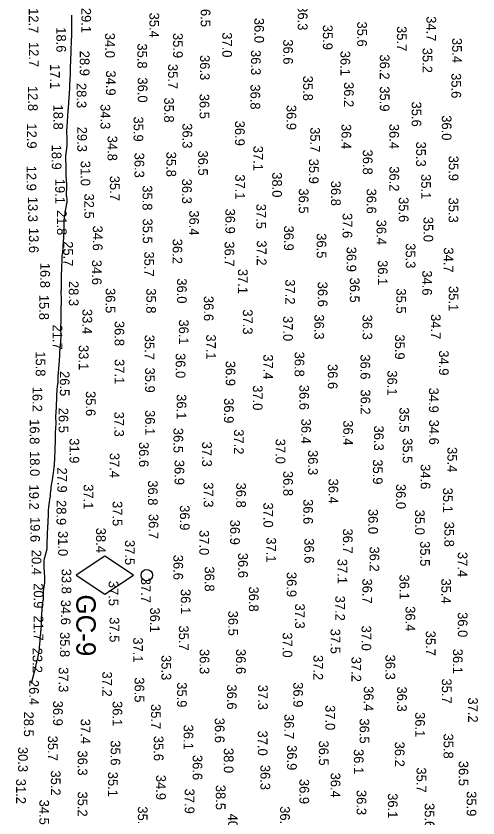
# Model space of a CAD drawing. Extents: x 1178573 to 1187098, y 693282 to 751751.
# Drawn here: x 1179031 to 1179627, y 707251 to 708287 of the extents above; entities that cross this region are included whole.
import ezdxf

# ---------------------------------------------------------------- set-up
doc = ezdxf.new("R2010")
doc.units = 0
for name, color, linetype in [('V-CHAN-NAID', 7, 'Continuous'), ('V-HYDS-MAJR', 7, 'Continuous'), ('V-HYDS-SOUN', 7, 'Continuous'), ('V-HYDS-SOUN-EXSS', 7, 'Continuous')]:
    doc.layers.add(name, color=color, linetype=linetype)

msp = doc.modelspace()

# ---------------------------------------------------------------- linework, layer by layer
at = {"layer": 'V-CHAN-NAID'}
msp.add_lwpolyline([(1179182.1, 707564.8), (1179145.2, 707589.4), (1179108.2, 707564.8), (1179145.2, 707540.1)], close=True, dxfattribs=at)
msp.add_circle((1179199.4, 707564.8), 7.39, dxfattribs=at)
at = {"layer": 'V-HYDS-MAJR'}
msp.add_lwpolyline([(1179050.4, 707425.1), (1179050.4, 707425.3), (1179055.1, 707441.7), (1179055.2, 707442.1), (1179055.3, 707442.6), (1179055.4, 707443.1), (1179055.5, 707443.6), (1179055.9, 707445.5), (1179056, 707445.9), (1179056.1, 707446.4), (1179056.3, 707446.9), (1179056.4, 707447.4), (1179059.2, 707459.6), (1179059.4, 707460.6), (1179059.6, 707461.6), (1179059.8, 707462.6), (1179060, 707463.6), (1179060.7, 707467.6), (1179060.8, 707468.6), (1179061, 707469.6), (1179061.1, 707470.6), (1179061.1, 707471.7), (1179061.6, 707479.9), (1179061.7, 707481.1), (1179061.8, 707482.2), (1179061.9, 707483.3), (1179062, 707484.4), (1179062.5, 707489), (1179062.6, 707490.1), (1179062.7, 707491.2), (1179062.8, 707492.3), (1179062.9, 707493.5), (1179063.3, 707499.6), (1179063.4, 707500.8), (1179063.4, 707502), (1179063.5, 707503.1), (1179063.5, 707504.3), (1179063.6, 707508.9), (1179063.7, 707510.1), (1179063.7, 707511.3), (1179063.8, 707512.4), (1179063.9, 707513.6), (1179064.3, 707520.8), (1179064.4, 707522.1), (1179064.6, 707523.4), (1179064.7, 707524.8), (1179064.9, 707526.1), (1179065.7, 707532.2), (1179065.9, 707533.1), (1179065.9, 707534.1), (1179066, 707535.1), (1179066, 707536.1), (1179066, 707540), (1179066, 707541), (1179066.1, 707541.9), (1179066.2, 707542.9), (1179066.3, 707543.9), (1179067.9, 707555.2), (1179068, 707555.8), (1179068, 707556.3), (1179068, 707556.9), (1179068, 707557.5), (1179067.9, 707559.9), (1179067.9, 707560.5), (1179067.8, 707561.1), (1179067.8, 707561.7), (1179067.7, 707562.3), (1179066.9, 707575), (1179066.8, 707576.1), (1179066.8, 707577.1), (1179066.8, 707578.2), (1179066.8, 707579.2), (1179067, 707583.4), (1179067.1, 707584.5), (1179067.2, 707585.5), (1179067.4, 707586.6), (1179067.7, 707587.6), (1179070.7, 707598.7), (1179070.7, 707598.8), (1179070.7, 707598.9), (1179070.7, 707599), (1179070.7, 707599.1), (1179070.8, 707599.6), (1179070.8, 707599.7), (1179070.8, 707599.7), (1179070.8, 707599.8), (1179070.8, 707599.9), (1179070.8, 707600.1), (1179070.8, 707600.2), (1179070.8, 707600.3), (1179070.8, 707600.3), (1179070.8, 707600.4), (1179071.4, 707621.7), (1179071.4, 707622.6), (1179071.5, 707623.4), (1179071.5, 707624.3), (1179071.6, 707625.2), (1179071.9, 707628.7), (1179071.9, 707629.5), (1179072, 707630.4), (1179072, 707631.3), (1179072.1, 707632.2), (1179072.4, 707644.9), (1179072.4, 707645.8), (1179072.4, 707646.7), (1179072.5, 707647.6), (1179072.6, 707648.5), (1179072.9, 707652.2), (1179073, 707653.1), (1179073.1, 707654), (1179073.2, 707654.9), (1179073.4, 707655.8), (1179074.8, 707665.3), (1179075, 707666.4), (1179075.1, 707667.5), (1179075.2, 707668.6), (1179075.3, 707669.7), (1179075.7, 707674.1), (1179075.8, 707675.2), (1179075.9, 707676.3), (1179076, 707677.4), (1179076.2, 707678.5), (1179078.1, 707690.6), (1179078.2, 707690.9), (1179078.2, 707691.1), (1179078.2, 707691.4), (1179078.2, 707691.6), (1179078.3, 707692.6), (1179078.4, 707692.9), (1179078.4, 707693.1), (1179078.4, 707693.4), (1179078.4, 707693.6), (1179079.8, 707703.8), (1179079.9, 707705.1), (1179080.1, 707706.4), (1179080.2, 707707.7), (1179080.3, 707708.9), (1179080.6, 707714.4), (1179080.7, 707715.5), (1179080.8, 707716.6), (1179080.8, 707717.7), (1179080.9, 707718.8), (1179081.1, 707723.1), (1179081.1, 707724.2), (1179081.2, 707725.3), (1179081.2, 707726.4), (1179081.2, 707727.5), (1179081.4, 707738.6), (1179081.4, 707739.5), (1179081.5, 707740.3), (1179081.5, 707741.1), (1179081.5, 707742), (1179081.5, 707745.3), (1179081.5, 707746.1), (1179081.5, 707747), (1179081.6, 707747.8), (1179081.6, 707748.6), (1179082.3, 707760.6), (1179082.3, 707761.4), (1179082.3, 707762.2), (1179082.3, 707762.9), (1179082.3, 707763.7), (1179082.1, 707766.7), (1179082.1, 707767.5), (1179082.1, 707768.3), (1179082.1, 707769), (1179082.1, 707769.8), (1179082.8, 707781.2), (1179082.8, 707782.4), (1179082.9, 707783.6), (1179082.9, 707784.9), (1179083, 707786.1), (1179083.2, 707791.2), (1179083.2, 707792.3), (1179083.3, 707793.4), (1179083.3, 707794.5), (1179083.4, 707795.6), (1179083.5, 707800.1), (1179083.6, 707801.2), (1179083.7, 707802.3), (1179083.8, 707803.4), (1179083.9, 707804.5), (1179084.8, 707811.9), (1179084.9, 707813.2), (1179085, 707814.5), (1179085.1, 707815.8), (1179085.1, 707817), (1179085.2, 707822.5), (1179085.2, 707823.6), (1179085.3, 707824.7), (1179085.3, 707825.8), (1179085.4, 707826.9), (1179085.9, 707831.4), (1179086, 707832.5), (1179086.1, 707833.7), (1179086.2, 707834.8), (1179086.2, 707835.9), (1179087, 707848.6), (1179087.1, 707849.6), (1179087.1, 707850.6), (1179087.2, 707851.6), (1179087.3, 707852.7), (1179087.6, 707856.7), (1179087.7, 707857.7), (1179087.8, 707858.8), (1179087.8, 707859.8), (1179087.9, 707860.8), (1179088.7, 707873.2), (1179088.8, 707874.1), (1179088.8, 707875), (1179088.8, 707875.9), (1179088.8, 707876.8), (1179088.6, 707880.4), (1179088.6, 707881.3), (1179088.5, 707882.2), (1179088.5, 707883.2), (1179088.6, 707884.1), (1179088.8, 707892.9), (1179088.8, 707894.4), (1179088.9, 707895.8), (1179088.9, 707897.3), (1179088.9, 707898.8), (1179088.8, 707904.7), (1179088.8, 707906.1), (1179088.8, 707907.6), (1179088.9, 707909), (1179088.9, 707910.4), (1179089.2, 707916.2), (1179089.2, 707917.6), (1179089.2, 707919), (1179089.2, 707920.5), (1179089.2, 707921.9), (1179089.1, 707930), (1179089.1, 707930.8), (1179089.1, 707931.5), (1179089.1, 707932.3), (1179089.2, 707933), (1179089.4, 707936), (1179089.4, 707936.8), (1179089.4, 707937.5), (1179089.5, 707938.3), (1179089.5, 707939), (1179089.4, 707945.2), (1179089.4, 707946.3), (1179089.4, 707947.4), (1179089.4, 707948.5), (1179089.5, 707949.6), (1179089.5, 707953.9), (1179089.5, 707955), (1179089.5, 707956.1), (1179089.6, 707957.2), (1179089.6, 707958.3), (1179090.2, 707975.5), (1179090.2, 707975.9), (1179090.3, 707976.4), (1179090.3, 707976.9), (1179090.4, 707977.3), (1179090.7, 707979.2), (1179090.8, 707979.7), (1179090.8, 707980.1), (1179090.9, 707980.6), (1179090.9, 707981.1), (1179092, 707996.8), (1179092.1, 707997.8), (1179092.2, 707998.8), (1179092.2, 707999.9), (1179092.3, 708000.9), (1179092.5, 708005.1), (1179092.5, 708006.1), (1179092.6, 708007.2), (1179092.6, 708008.2), (1179092.6, 708009.2), (1179092.9, 708023.7), (1179092.9, 708024.7), (1179093, 708025.6), (1179093.1, 708026.6), (1179093.3, 708027.5), (1179093.9, 708031.4), (1179094.1, 708032.3), (1179094.2, 708033.3), (1179094.4, 708034.2), (1179094.6, 708035.2), (1179096.3, 708044.9), (1179096.5, 708046), (1179096.6, 708047.2), (1179096.6, 708048.3), (1179096.5, 708049.5), (1179096.1, 708054), (1179096, 708055.2), (1179096, 708056.3), (1179096, 708057.5), (1179096, 708058.6), (1179096.3, 708063.9), (1179096.4, 708065.2), (1179096.4, 708066.4), (1179096.4, 708067.7), (1179096.3, 708069), (1179095.3, 708081.6), (1179095.3, 708082.3), (1179095.3, 708082.9), (1179095.3, 708083.6), (1179095.3, 708084.3), (1179095.5, 708087), (1179095.5, 708087.7), (1179095.5, 708088.4), (1179095.5, 708089.1), (1179095.5, 708089.7), (1179095.1, 708106.5), (1179095.1, 708106.7), (1179095.1, 708106.9), (1179095.1, 708107.2), (1179095.1, 708107.4), (1179095.1, 708108.2), (1179095.2, 708108.5), (1179095.2, 708108.7), (1179095.2, 708108.9), (1179095.2, 708109.1), (1179096.5, 708119.6), (1179096.7, 708121.4), (1179096.8, 708123.2), (1179096.8, 708125.1), (1179096.8, 708126.9), (1179096.4, 708139.9), (1179096.4, 708139.9), (1179096.4, 708140), (1179096.4, 708140), (1179096.4, 708140), (1179096.4, 708140.2), (1179096.4, 708140.2), (1179096.4, 708140.3), (1179096.4, 708140.3), (1179096.4, 708140.3), (1179096.5, 708142.4), (1179096.6, 708142.7), (1179096.6, 708143), (1179096.6, 708143.4), (1179096.6, 708143.7), (1179098, 708164.5), (1179098.1, 708164.8), (1179098.1, 708165.1), (1179098.1, 708165.5), (1179098.1, 708165.8), (1179098.2, 708167.1), (1179098.2, 708167.4), (1179098.3, 708167.8), (1179098.3, 708168.1), (1179098.3, 708168.4), (1179100, 708193.6), (1179100, 708193.7), (1179100, 708193.9), (1179100, 708194), (1179100, 708194.2), (1179100.1, 708194.8), (1179100.1, 708194.9), (1179100.1, 708195), (1179100.1, 708195.2), (1179100.1, 708195.3), (1179100.1, 708196.2), (1179100.1, 708196.4), (1179100.1, 708196.6), (1179100.1, 708196.7), (1179100.1, 708196.9), (1179100.8, 708212.7), (1179100.9, 708214.6), (1179100.9, 708216.5), (1179101, 708218.3), (1179101.1, 708220.2), (1179101.4, 708229.5), (1179101.4, 708230.5), (1179101.5, 708231.5), (1179101.5, 708232.5), (1179101.5, 708233.4), (1179101.7, 708237.3), (1179101.7, 708238.3), (1179101.7, 708239.2), (1179101.8, 708240.2), (1179101.8, 708241.2), (1179102.4, 708256.7), (1179102.4, 708257.9), (1179102.5, 708259.1), (1179102.5, 708260.3), (1179102.5, 708261.6), (1179102.5, 708266.4), (1179102.5, 708267.7), (1179102.6, 708268.9), (1179102.6, 708270.1), (1179102.6, 708271.3), (1179102.8, 708281.3), (1179102.8, 708282.1), (1179102.8, 708282.9), (1179102.8, 708283.8), (1179102.8, 708284.6), (1179102.8, 708287.9)], dxfattribs=at)

# ---------------------------------------------------------------- texts
at = {"layer": 'V-CHAN-NAID'}
msp.add_text('GC-9', height=25, rotation=270, dxfattribs=at).set_placement((1179108.5, 707539.8))
at = {"layer": 'V-HYDS-SOUN'}
for s, p in [('29.1 ', (1179115, 708297.5)), ('36.5 ', (1179269.1, 708305.4)), ('36.3 ', (1179394.4, 708300.9)), ('12.7 ', (1179047.1, 708297.2)), ('35.4 ', (1179202.9, 708291.4)), ('34.7 ', (1179560.5, 708286.7)), ('36.0 ', (1179338.3, 708284.6)), ('35.6 ', (1179471.1, 708279.9)), ('18.6 ', (1179082.7, 708272.5)), ('37.0 ', (1179296.9, 708266)), ('35.9 ', (1179426.8, 708275.7)), ('34.0 ', (1179145.7, 708265.3)), ('35.9 ', (1179233.4, 708265.1)), ('12.7 ', (1179047.3, 708253.5)), ('34.9 ', (1179146.8, 708216.7)), ('36.0 ', (1179187.8, 708207.7)), ('35.8 ', (1179401.3, 708209.9)), ('35.6 ', (1179592.7, 708213.2)), ('12.8 ', (1179046.1, 708196.7)), ('28.3 ', (1179109, 708200.5)), ('36.8 ', (1179333.3, 708198.7)), ('36.2 ', (1179454.1, 708201.7)), ('35.9 ', (1179500.3, 708196.2)), ('36.5 ', (1179267.6, 708186.6)), ('34.3 ', (1179139.7, 708173.2)), ('35.8 ', (1179221.9, 708181.8)), ('35.6 ', (1179541.4, 708176.5)), ('18.8 ', (1179078.9, 708172.6)), ('36.9 ', (1179379.9, 708172.2)), ('35.9 ', (1179182.4, 708157.2)), ('36.0 ', (1179580.3, 708158.8)), ('12.9 ', (1179044.8, 708148.3)), ('29.3 ', (1179109.7, 708144)), ('36.3 ', (1179245.5, 708148.5)), ('36.9 ', (1179313.4, 708151.8)), ('35.7 ', (1179410.5, 708143.4)), ('36.4 ', (1179450.8, 708147.5)), ('36.4 ', (1179512.6, 708147.7)), ('34.8 ', (1179148.8, 708132.4)), ('35.3 ', (1179547.2, 708124.8)), ('18.9 ', (1179076.8, 708120.9)), ('36.3 ', (1179183.6, 708110.5)), ('35.8 ', (1179224.8, 708111.7)), ('36.5 ', (1179265.8, 708113.3)), ('37.1 ', (1179337, 708119.4)), ('36.8 ', (1179478.4, 708114.5)), ('35.9 ', (1179408.8, 708102.7)), ('35.9 ', (1179589.3, 708106.5)), ('12.9 ', (1179044.3, 708093.7)), ('31.0 ', (1179114.1, 708100)), ('36.2 ', (1179512.7, 708092.9)), ('35.7 ', (1179151.8, 708080.7)), ('37.1 ', (1179313.6, 708082.5)), ('38.0 ', (1179361.4, 708085.2)), ('35.1 ', (1179553.7, 708082.8)), ('19.1 ', (1179081.2, 708076.8)), ('36.3 ', (1179245, 708076.9)), ('36.8 ', (1179437.3, 708074.2)), ('35.8 ', (1179194, 708068.3)), ('36.5 ', (1179395.7, 708064.3)), ('36.6 ', (1179483.3, 708064.1)), ('13.3 ', (1179046.1, 708053.5)), ('32.5 ', (1179118.8, 708057.7)), ('35.6 ', (1179524.8, 708053.1)), ('35.3 ', (1179589.1, 708052.5)), ('36.9 ', (1179300.9, 708038.2)), ('37.5 ', (1179340.8, 708044.5)), ('21.8 ', (1179083.5, 708036.3)), ('36.4 ', (1179254.3, 708036)), ('37.6 ', (1179452.2, 708032.5)), ('35.0 ', (1179556.7, 708027.6)), ('35.5 ', (1179194.3, 708025.4)), ('36.4 ', (1179496.1, 708023.9)), ('13.6 ', (1179047.3, 708013.4)), ('34.6 ', (1179129.8, 708016.3)), ('36.9 ', (1179376.6, 708016.3)), ('36.2 ', (1179232.8, 707999.3)), ('37.2 ', (1179341.5, 707997.2)), ('36.5 ', (1179418.8, 708006.4)), ('25.7 ', (1179091.7, 707996.1)), ('36.7 ', (1179299.9, 707995.9)), ('36.9 ', (1179457.4, 707989)), ('35.3 ', (1179533.8, 707993.5)), ('34.7 ', (1179582.8, 707988.1)), ('35.7 ', (1179196.2, 707982.9)), ('16.8 ', (1179061.9, 707968.2)), ('34.6 ', (1179128.7, 707972.1)), ('36.1 ', (1179497.8, 707971.7)), ('37.1 ', (1179317.2, 707960.4)), ('34.6 ', (1179555.1, 707958.5)), ('36.0 ', (1179238.5, 707948.2)), ('37.2 ', (1179378.3, 707946.9)), ('36.5 ', (1179461.6, 707949.2)), ('28.3 ', (1179098.8, 707944.8)), ('36.5 ', (1179146.3, 707935.6)), ('35.8 ', (1179198.8, 707935.3)), ('36.6 ', (1179420.2, 707943.8)), ('35.5 ', (1179521.6, 707935.1)), ('35.1 ', (1179589.2, 707938.2)), ('15.8 ', (1179060.6, 707926.9)), ('36.6 ', (1179273.1, 707925.4)), ('33.4 ', (1179116.4, 707908.6)), ('37.3 ', (1179323.5, 707908.1)), ('36.8 ', (1179157.9, 707893.2)), ('36.1 ', (1179240.9, 707895.1)), ('37.0 ', (1179375.5, 707899.5)), ('36.3 ', (1179415.8, 707901.6)), ('36.3 ', (1179478, 707901.3)), ('34.7 ', (1179566.3, 707902)), ('21.7 ', (1179078, 707888.5)), ('35.7 ', (1179196.8, 707875.3)), ('37.1 ', (1179276.1, 707875.7)), ('35.9 ', (1179519.9, 707875.7)), ('33.1 ', (1179111.7, 707862.1)), ('15.8 ', (1179056.1, 707853.9)), ('36.0 ', (1179236.8, 707851.6)), ('36.8 ', (1179390.3, 707853.5)), ('34.9 ', (1179576.7, 707855.2)), ('37.1 ', (1179158, 707843.9)), ('36.9 ', (1179301.3, 707841.6)), ('37.4 ', (1179349.9, 707850)), ('36.6 ', (1179475.3, 707850)), ('35.9 ', (1179197.3, 707832.9)), ('36.6 ', (1179433.2, 707837.5)), ('26.5 ', (1179087.2, 707828.4)), ('36.1 ', (1179510.1, 707829.3)), ('36.6 ', (1179396.4, 707810.6)), ('16.2 ', (1179051.9, 707808.2)), ('35.6 ', (1179120.8, 707802.6)), ('37.0 ', (1179336.4, 707810.1)), ('36.2 ', (1179475.6, 707804.7)), ('34.9 ', (1179563.7, 707807)), ('36.1 ', (1179238, 707798.5)), ('36.9 ', (1179299.2, 707793.4)), ('26.5 ', (1179085.6, 707781)), ('35.5 ', (1179525.6, 707781.6)), ('37.3 ', (1179157.5, 707776)), ('36.1 ', (1179197.4, 707778)), ('16.8 ', (1179048.4, 707766.2)), ('36.4 ', (1179398.9, 707766.9)), ('36.4 ', (1179453.1, 707764.8)), ('34.6 ', (1179564, 707765.6)), ('36.5 ', (1179233.9, 707755)), ('37.2 ', (1179312.1, 707753.2)), ('36.3 ', (1179492.8, 707758)), ('31.9 ', (1179099.7, 707741.6)), ('37.0 ', (1179365.8, 707741)), ('35.5 ', (1179529.9, 707741.7)), ('36.6 ', (1179189.4, 707736.8)), ('37.3 ', (1179270.9, 707737.2)), ('35.4 ', (1179587.6, 707730.2)), ('18.0 ', (1179048.6, 707725)), ('37.4 ', (1179151.7, 707722.7)), ('36.3 ', (1179407.7, 707726.4)), ('36.9 ', (1179235.3, 707713.7)), ('35.9 ', (1179491.4, 707714.4)), ('34.6 ', (1179553, 707708.2)), ('27.9 ', (1179084, 707703.8)), ('36.8 ', (1179375.6, 707699.4)), ('36.8 ', (1179201, 707687.3)), ('36.4 ', (1179434.1, 707689.5)), ('19.2 ', (1179047.6, 707681.8)), ('37.1 ', (1179117.9, 707682.2)), ('37.3 ', (1179272.9, 707684.7)), ('36.8 ', (1179314.9, 707684.3)), ('36.0 ', (1179521.3, 707682.6)), ('35.1 ', (1179581.9, 707677.7)), ('28.9 ', (1179082.9, 707661.8)), ('37.5 ', (1179155.3, 707660.5)), ('36.9 ', (1179242.2, 707655.1)), ('37.0 ', (1179350, 707658.6)), ('36.6 ', (1179401.5, 707663)), ('36.0 ', (1179485.4, 707650.3)), ('35.0 ', (1179545.7, 707649.3)), ('19.6 ', (1179049.1, 707639.9)), ('36.7 ', (1179201.9, 707643.8)), ('36.9 ', (1179307.1, 707636.4)), ('38.4 ', (1179134, 707626)), ('36.7 ', (1179452.7, 707625)), ('35.8 ', (1179583.7, 707633.8)), ('31.0 ', (1179085, 707621.8)), ('37.0 ', (1179267.3, 707623)), ('37.1 ', (1179353.8, 707613.6)), ('37.5 ', (1179171.4, 707610.2)), ('36.6 ', (1179402.9, 707612.4)), ('35.5 ', (1179552.4, 707608.7)), ('20.4 ', (1179050.8, 707597.5)), ('36.6 ', (1179317.4, 707593.6)), ('36.2 ', (1179487.1, 707601.8)), ('37.4 ', (1179600.9, 707594.7)), ('36.6 ', (1179233.8, 707591.1)), ('37.1 ', (1179445.7, 707585.8)), ('33.8 ', (1179089.5, 707573.1)), ('36.8 ', (1179274.2, 707576)), ('36.9 ', (1179380.2, 707568.9)), ('36.1 ', (1179525.7, 707565.6)), ('20.9 ', (1179053.5, 707554.3)), ('36.7 ', (1179477.8, 707560.4)), ('35.4 ', (1179579.7, 707560.4)), ('36.1 ', (1179243.4, 707546.9)), ('36.8 ', (1179331.3, 707550.1)), ('34.6 ', (1179088.6, 707533)), ('37.2 ', (1179442.8, 707538.3)), ('36.1 ', (1179203.7, 707523)), ('37.3 ', (1179390.9, 707528.1)), ('36.4 ', (1179533.5, 707524.6)), ('21.7 ', (1179053.4, 707512.6)), ('37.5 ', (1179151.4, 707510.4)), ('36.5 ', (1179304.6, 707518.9)), ('36.0 ', (1179601, 707517)), ('35.7 ', (1179240.9, 707499.8)), ('37.0 ', (1179476.7, 707499.6)), ('35.8 ', (1179087.4, 707491.3)), ('37.0 ', (1179374.8, 707490.8)), ('37.5 ', (1179436.7, 707495.6)), ('35.7 ', (1179559.7, 707493)), ('37.1 ', (1179181.9, 707484.4)), ('23.2 ', (1179052.1, 707471)), ('36.3 ', (1179267.7, 707469.4)), ('36.6 ', (1179314.7, 707469.4)), ('36.1 ', (1179594.7, 707469.7)), ('35.3 ', (1179218.4, 707461.5)), ('37.2 ', (1179414.5, 707461.6)), ('37.2 ', (1179463.7, 707459.4)), ('36.3 ', (1179507.6, 707462.1)), ('37.3 ', (1179085.7, 707445.9)), ('37.2 ', (1179142, 707440.3)), ('26.4 ', (1179047.6, 707429.4)), ('36.5 ', (1179183.7, 707432.8)), ('35.7 ', (1179580.4, 707431.3)), ('35.9 ', (1179238.6, 707426.4)), ('36.6 ', (1179303, 707423.6)), ('37.3 ', (1179343.1, 707423.2)), ('36.9 ', (1179388.6, 707426.5)), ('36.4 ', (1179479.6, 707421.3)), ('36.3 ', (1179522.6, 707420.9)), ('37.2 ', (1179614.3, 707406.8)), ('36.9 ', (1179078.5, 707402.6)), ('36.1 ', (1179155.3, 707402.1)), ('35.7 ', (1179204.9, 707398.3)), ('37.0 ', (1179430.1, 707396.9)), ('28.5 ', (1179040.8, 707388.5)), ('36.1 ', (1179546, 707387.9)), ('37.4 ', (1179114.1, 707379.3)), ('36.6 ', (1179287.3, 707380.5)), ('36.7 ', (1179377, 707385.4)), ('36.5 ', (1179474.2, 707379.7)), ('36.1 ', (1179247, 707371.7)), ('35.7 ', (1179071.8, 707357.4)), ('35.6 ', (1179208.5, 707357.2)), ('37.0 ', (1179342.8, 707364)), ('35.8 ', (1179582.6, 707360.2)), ('35.6 ', (1179152.8, 707351.4)), ('36.9 ', (1179380.6, 707345.2)), ('36.5 ', (1179421.6, 707351.2)), ('36.2 ', (1179519.7, 707349.7)), ('30.3 ', (1179033.3, 707342.9)), ('36.3 ', (1179110.3, 707338.3)), ('38.0 ', (1179298.9, 707341.5)), ('36.1 ', (1179466.8, 707340.2)), ('36.6 ', (1179258.7, 707332.5)), ('36.5 ', (1179602.1, 707324.9)), ('36.3 ', (1179346.2, 707319.7)), ('35.7 ', (1179547.7, 707316.4)), ('35.2 ', (1179075.6, 707312.5)), ('35.1 ', (1179149.5, 707310.8)), ('34.9 ', (1179211.5, 707306.8)), ('36.4 ', (1179436.9, 707309.7)), ('31.2 ', (1179030.8, 707301.7)), ('38.5 ', (1179288.6, 707293.9)), ('36.9 ', (1179396.5, 707301.5)), ('35.2 ', (1179110.3, 707285.3)), ('37.9 ', (1179248.5, 707289)), ('36.3 ', (1179470.4, 707287.3)), ('36.1 ', (1179510.7, 707283.1)), ('35.9 ', (1179612.4, 707285.7)), ('34.5 ', (1179060.8, 707274.8)), ('35.0 ', (1179187.9, 707266.1)), ('36.6 ', (1179371.6, 707266.3)), ('35.6 ', (1179558.3, 707270.4)), ('40.0 ', (1179304.3, 707256.7))]:
    msp.add_text(s, height=12.5, rotation=270, dxfattribs=at).set_placement(p)
at = {"layer": 'V-HYDS-SOUN-EXSS'}
for s, p in [('35.7 ', (1179522.4, 708274)), ('36.6 ', (1179375.6, 708256.9)), ('35.4 ', (1179593.7, 708258.7)), ('35.8 ', (1179187.3, 708251.6)), ('35.2 ', (1179555.5, 708246)), ('28.9 ', (1179113, 708242.1)), ('36.3 ', (1179268.2, 708236.6)), ('36.3 ', (1179334, 708243.1)), ('36.1 ', (1179449.5, 708242.1)), ('36.2 ', (1179500.3, 708237.4)), ('17.1 ', (1179074.7, 708225.1)), ('35.7 ', (1179226.9, 708225.1)), ('37.5 ', (1179150.2, 707557.5)), ('37.7 ', (1179192, 707561.4))]:
    msp.add_text(s, height=12.5, rotation=270, dxfattribs=at).set_placement(p)

doc.saveas('drawing.dxf')
